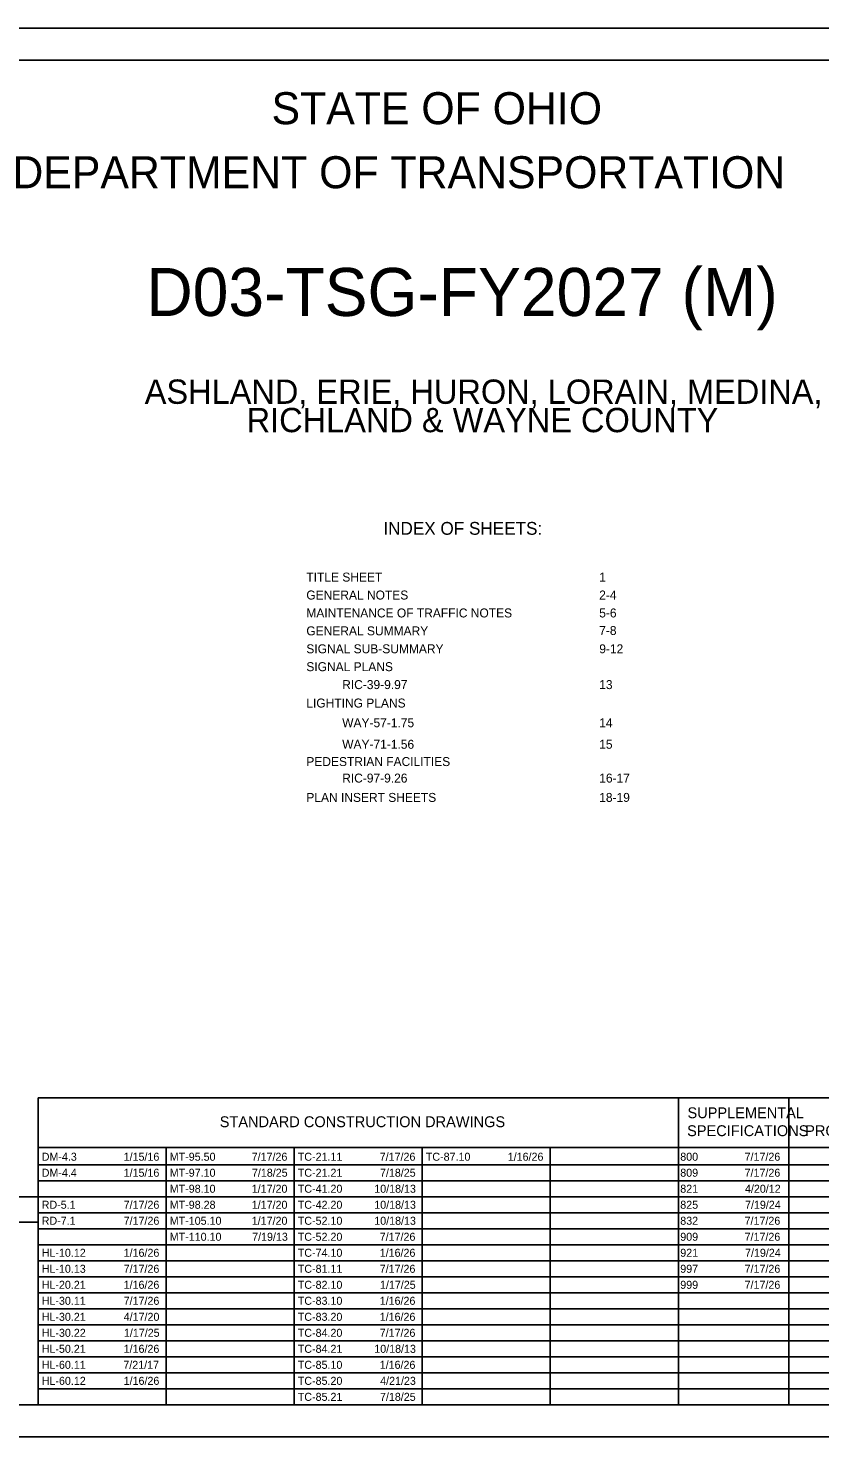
# Model space of a CAD drawing. Extents: x 0 to 34, y 0 to 22.
# Drawn here: x 9.99 to 22.36, y 0 to 22 of the extents above; entities that cross this region are included whole.
import ezdxf

# ---------------------------------------------------------------- set-up
doc = ezdxf.new("R2010")
doc.units = 0
for name, color, linetype in [('Default', 7, 'Continuous'), ('SH_Border', 7, 'Continuous'), ('SH_Cut_Line', 7, 'Continuous'), ('SH_Data', 7, 'Continuous'), ('SH_Text', 7, 'Continuous')]:
    doc.layers.add(name, color=color, linetype=linetype)

msp = doc.modelspace()

# ---------------------------------------------------------------- linework, layer by layer
at = {"layer": 'SH_Border'}
msp.add_lwpolyline([(1.5, 21.5), (33.5, 21.5), (33.5, 0.5), (1.5, 0.5)], close=True, dxfattribs=at)
at = {"layer": 'SH_Cut_Line'}
msp.add_lwpolyline([(0, 0), (34, 0), (34, 22), (0, 22)], close=True, dxfattribs=at)
at = {"layer": 'SH_Data'}
for p, q in [((10.15, 5.292), (23.6, 5.292)), ((10.15, 0.5), (10.15, 5.292)), ((20.15, 0.5), (20.15, 5.292)), ((21.875, 0.5), (21.875, 5.292)), ((10.15, 4.521), (23.6, 4.521)), ((12.15, 0.5), (12.15, 4.521)), ((14.15, 0.5), (14.15, 4.521)), ((16.15, 0.5), (16.15, 4.521)), ((18.15, 0.5), (18.15, 4.521)), ((10.15, 4.25), (23.6, 4.25)), ((10.15, 4), (23.6, 4)), ((7.35, 3.75), (10.15, 3.75)), ((10.15, 3.75), (23.6, 3.75)), ((10.15, 3.75), (10.15, 0.5)), ((7.35, 3.35), (10.15, 3.35)), ((10.15, 3.5), (23.6, 3.5)), ((10.15, 3.25), (23.6, 3.25)), ((10.15, 3), (23.6, 3)), ((10.15, 2.75), (23.6, 2.75)), ((10.15, 2.5), (23.6, 2.5)), ((10.15, 2.25), (23.6, 2.25)), ((10.15, 2), (23.6, 2)), ((10.15, 1.75), (23.6, 1.75)), ((10.15, 1.5), (23.6, 1.5)), ((10.15, 1.25), (23.6, 1.25)), ((10.15, 1), (23.6, 1)), ((10.15, 0.75), (23.6, 0.75)), ((7.35, 0.5), (10.15, 0.5))]:
    msp.add_line(p, q, dxfattribs=at)

# ---------------------------------------------------------------- texts
at = {"layer": 'Default'}
for s, p in [('DM-4.3', (10.205, 4.312)), ('1/15/16', (11.485, 4.312)), ('MT-95.50', (12.205, 4.312)), ('7/17/26', (13.485, 4.312)), ('TC-21.11', (14.205, 4.312)), ('7/17/26', (15.485, 4.312)), ('TC-87.10', (16.205, 4.312)), ('1/16/26', (17.485, 4.312)), ('800', (20.18, 4.312)), ('7/17/26', (21.185, 4.312)), ('DM-4.4', (10.205, 4.062)), ('1/15/16', (11.485, 4.062)), ('MT-97.10', (12.205, 4.062)), ('7/18/25', (13.489, 4.062)), ('TC-21.21', (14.205, 4.062)), ('7/18/25', (15.489, 4.062)), ('809', (20.18, 4.062)), ('7/17/26', (21.185, 4.062)), ('MT-98.10', (12.205, 3.812)), ('1/17/20', (13.486, 3.812)), ('TC-41.20', (14.205, 3.812)), ('10/18/13', (15.4, 3.812)), ('821', (20.18, 3.812)), ('4/20/12', (21.191, 3.812)), ('RD-5.1', (10.205, 3.562)), ('7/17/26', (11.485, 3.562)), ('MT-98.28', (12.205, 3.562)), ('1/17/20', (13.486, 3.562)), ('TC-42.20', (14.205, 3.562)), ('10/18/13', (15.4, 3.562)), ('825', (20.18, 3.562)), ('7/19/24', (21.192, 3.562)), ('RD-7.1', (10.205, 3.312)), ('7/17/26', (11.485, 3.312)), ('MT-105.10', (12.205, 3.312)), ('1/17/20', (13.486, 3.312)), ('TC-52.10', (14.205, 3.312)), ('10/18/13', (15.4, 3.312)), ('832', (20.18, 3.312)), ('7/17/26', (21.185, 3.312)), ('MT-110.10', (12.205, 3.062)), ('7/19/13', (13.492, 3.062)), ('TC-52.20', (14.205, 3.062)), ('7/17/26', (15.485, 3.062)), ('909', (20.18, 3.062)), ('7/17/26', (21.185, 3.062)), ('HL-10.12', (10.205, 2.812)), ('1/16/26', (11.485, 2.812)), ('TC-74.10', (14.205, 2.812)), ('1/16/26', (15.485, 2.812)), ('921', (20.18, 2.812)), ('7/19/24', (21.192, 2.812)), ('HL-10.13', (10.205, 2.562)), ('7/17/26', (11.485, 2.562)), ('TC-81.11', (14.205, 2.562)), ('7/17/26', (15.485, 2.562)), ('997', (20.18, 2.562)), ('7/17/26', (21.185, 2.562)), ('HL-20.21', (10.205, 2.312)), ('1/16/26', (11.485, 2.312)), ('TC-82.10', (14.205, 2.312)), ('1/17/25', (15.489, 2.312)), ('999', (20.18, 2.312)), ('7/17/26', (21.185, 2.312)), ('HL-30.11', (10.205, 2.062)), ('7/17/26', (11.485, 2.062)), ('TC-83.10', (14.205, 2.062)), ('1/16/26', (15.485, 2.062)), ('HL-30.21', (10.205, 1.812)), ('4/17/20', (11.486, 1.812)), ('TC-83.20', (14.205, 1.812)), ('1/16/26', (15.485, 1.812)), ('HL-30.22', (10.205, 1.562)), ('1/17/25', (11.489, 1.562)), ('TC-84.20', (14.205, 1.562)), ('7/17/26', (15.485, 1.562)), ('HL-50.21', (10.205, 1.312)), ('1/16/26', (11.485, 1.312)), ('TC-84.21', (14.205, 1.312)), ('10/18/13', (15.4, 1.312)), ('HL-60.11', (10.205, 1.062)), ('7/21/17', (11.48, 1.062)), ('TC-85.10', (14.205, 1.062)), ('1/16/26', (15.485, 1.062)), ('HL-60.12', (10.205, 0.812)), ('1/16/26', (11.485, 0.812)), ('TC-85.20', (14.205, 0.812)), ('4/21/23', (15.492, 0.812)), ('TC-85.21', (14.205, 0.562)), ('7/18/25', (15.489, 0.562))]:
    msp.add_text(s, height=0.125, dxfattribs=at).set_placement(p)
at = {"layer": 'SH_Text'}
for s, height, p in [('STATE OF OHIO', 0.5, (13.795, 20.5)), ('DEPARTMENT OF TRANSPORTATION', 0.5, (9.747, 19.5)), ('D03-TSG-FY2027 (M)', 0.75, (11.839, 17.505)), ('ASHLAND, ERIE, HURON, LORAIN, MEDINA, ', 0.38, (11.814, 16.133)), ('RICHLAND & WAYNE COUNTY', 0.38, (13.406, 15.69)), ('INDEX OF SHEETS:', 0.2, (15.542, 14.088)), ('TITLE SHEET', 0.14, (14.339, 13.357)), ('1', 0.14, (18.914, 13.357)), ('GENERAL NOTES', 0.14, (14.339, 13.077)), ('2-4', 0.14, (18.914, 13.077)), ('MAINTENANCE OF TRAFFIC NOTES', 0.14, (14.339, 12.797)), ('5-6', 0.14, (18.914, 12.797)), ('GENERAL SUMMARY', 0.14, (14.339, 12.517)), ('7-8', 0.14, (18.914, 12.523)), ('SIGNAL SUB-SUMMARY', 0.14, (14.339, 12.237)), ('9-12', 0.14, (18.915, 12.237)), ('SIGNAL PLANS', 0.14, (14.339, 11.958)), ('RIC-39-9.97', 0.14, (14.899, 11.678)), ('13', 0.14, (18.914, 11.678)), ('LIGHTING PLANS', 0.14, (14.339, 11.39)), ('WAY-57-1.75', 0.14, (14.899, 11.082)), ('14', 0.14, (18.914, 11.082)), ('WAY-71-1.56', 0.14, (14.899, 10.746)), ('15', 0.14, (18.914, 10.746)), ('PEDESTRIAN FACILITIES', 0.14, (14.339, 10.476)), ('RIC-97-9.26', 0.14, (14.899, 10.218)), ('16-17', 0.14, (18.914, 10.218)), ('PLAN INSERT SHEETS', 0.14, (14.339, 9.916)), ('18-19', 0.14, (18.914, 9.916)), ('SUPPLEMENTAL', 0.17, (20.293, 4.976)), ('STANDARD CONSTRUCTION DRAWINGS', 0.17, (12.986, 4.836)), ('SPECIFICATIONS', 0.17, (20.287, 4.696)), ('PROVISIONS', 0.17, (22.132, 4.696))]:
    msp.add_text(s, height=height, dxfattribs=at).set_placement(p)

doc.saveas('drawing.dxf')
